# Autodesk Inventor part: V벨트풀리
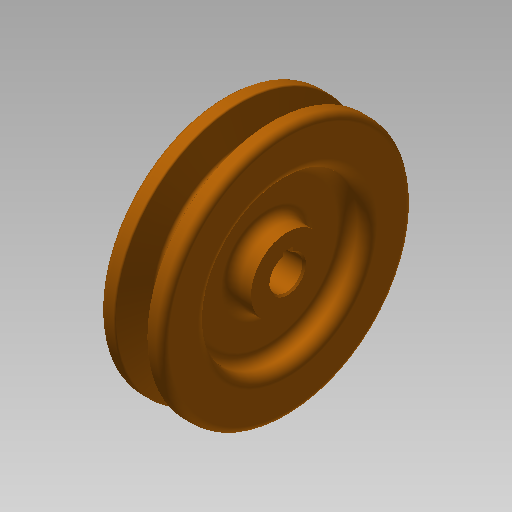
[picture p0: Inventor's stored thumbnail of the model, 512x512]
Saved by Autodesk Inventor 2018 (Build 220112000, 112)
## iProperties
Created: 2015-11
Part Number: V벨트풀리
Material: 알루미늄 6061
Document SubType Name: Modeling
Designer: mduedu
Density: 1 g/cm^3
Appearance: 주황색
Author: mduedu
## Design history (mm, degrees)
sketch "스케치1"
  geometry: L1 (-9.5, 0)-(9.5, 0); L2 (0, 0)-(0, 37.7); L3 (-4.825, 37.7)-(-9.5, 37.7); L4 (-9.5, 37.7)-(-9.5, 0); L5 (0, 28.7)-(-2.074, 28.7); L6 (-2.074, 28.7)-(-4.825, 37.7); L7 (4.825, 37.7)-(9.5, 37.7); L8 (9.5, 37.7)-(9.5, 0); L9 (0, 28.7)-(2.074, 28.7); L10 (2.074, 28.7)-(4.825, 37.7); L11 (-9.5, 35)-(9.5, 35); 3 further points
  constraints: 22 end point, 7 point on line, 4 perpendicular, 3 symmetric about line, 1 coincident, 1 horizontal, 1 horizontal alignment, 1 midpoint, 1 vertical
  dimensions: "d0" = 19 distance of L1.start L1.end; "d2" = 75.4 diameter of L2.end L1 (derived); "d3" = 34 deg angle of L10 L6; "d4" = 6.3 distance between parallel lines of L11 L9; "d5" = 2.7 distance between parallel lines of L7 L11; "d6" = 8 distance of point (4, 35) point (-4, 35); "d7" = 70 diameter of L11 L1
revolve "회전1" sketch "스케치1" stored, may be unused: angle "d8" = 90 deg
sketch "스케치2"
  geometry: C1 r 24 at (0, 0); C2 r 11 at (0, 0); 1 further point
  constraints: 2 centre point, 2 coincident
  dimensions: "d9" = 48 diameter of C1; "d10" = 22 diameter of C2
extrude "돌출1" cut sketch "스케치2" distance "d11" = 6; taper "d12" = 0 deg
fillet "모깎기1" dims "d13" = 3
fillet "모깎기2" dims "d14" = 3
fillet "모깎기3" dims "d15" = 1, "d16" = 0.5, "d17" = 2
hole "구멍1" diameter "d20" = 10; stored, may be unused: countersink angle "d24" = 90 deg, drill point angle "d26" = 118 deg; dims "d18" = 10, "d19" = 10, "d21" = 6, "d22" = 4, "d23" = 2, "d25" = 8
sketch "스케치3"
  geometry: L1 (-1.5, 0)-(1.5, 0); L2 (1.5, 0)-(1.5, 6.4); L3 (1.5, 6.4)-(-1.5, 6.4); L4 (-1.5, 6.4)-(-1.5, 0); 2 further points
  constraints: 8 end point, 2 parallel, 1 coincident, 1 horizontal, 1 midpoint, 1 perpendicular
  dimensions: "d27" = 3 distance of L2.end L3.end; "d29" = 6.4 distance of L3.end L1.start
extrude "돌출2" cut sketch "스케치3" extent not by distance; stored distance "d30" = 6; taper "d31" = 0 deg
chamfer "모따기1" distance "d32" = 0.5; stored, may be unused: second distance "d33" = 2, angle "d34" = 45 deg
node "솔리드1"
mirror "대칭1"
